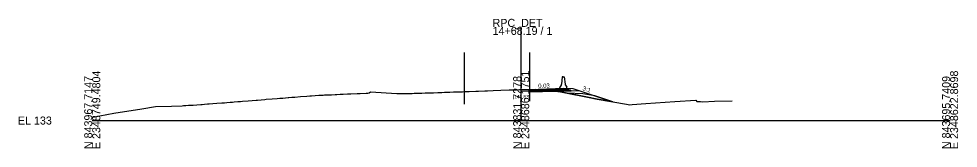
# Model space of a CAD drawing. Extents: x -26 to 2348728, y -10 to 843971.
# Drawn here: x -25.7 to 302.8, y 5990.3 to 6035.6 of the extents above; entities that cross this region are included whole.
import ezdxf

# ---------------------------------------------------------------- set-up
doc = ezdxf.new("R2010")
doc.units = 0
for name, color, linetype in [('Default', 7, 'Continuous'), ('Exist Cross Section Cell', 7, 'Continuous'), ('Exist XS Center Line Elevation Label', 7, 'Continuous'), ('Exist XS Ground Line', 7, 'Continuous'), ('Old_Level_1', 7, 'Continuous'), ('Prop CMT Pvmt Course 1', 7, 'Continuous'), ('Prop CMT Pvmt Course 2', 7, 'Continuous'), ('Prop CMT Pvmt Course 3', 7, 'Continuous'), ('Prop CMT Pvmt Surface', 7, 'Continuous'), ('Prop CMT Pvmt Surface Shoulder', 7, 'Continuous'), ('Prop CMT Shld Paved Course 1', 7, 'Continuous'), ('Prop CMT Shld Paved Course 2', 7, 'Continuous'), ('Prop CMT Shld Paved Course 3', 7, 'Continuous'), ('Prop CMT Slope Grass', 7, 'Continuous'), ('Prop CMT Subgrade Earthwork', 7, 'Continuous'), ('Prop XS Earthwork Shape', 7, 'Continuous'), ('Prop XS Side Slope Text', 7, 'Continuous'), ('Scratch_Level_2', 7, 'Continuous'), ('Scratch_Level_6', 7, 'Continuous'), ('Typical Median Barrier CELL', 7, 'Continuous')]:
    doc.layers.add(name, color=color, linetype=linetype)

# ---------------------------------------------------------------- blocks, each defined once
blk = doc.blocks.new('TYPE T DOUBLE FACE BARRIER')
at = {"layer": 'Typical Median Barrier CELL'}
for p, q in [((-0.33, 3.83), (-0.6, 1.3)), ((0, 3.83), (-0.33, 3.83)), ((0, 3.83), (0.33, 3.83)), ((0.33, 3.83), (0.6, 1.3)), ((-0.75, 0.91), (-1.21, 0.25)), ((-1.21, -0.17), (-1.21, 0.25)), ((0, 0), (0, 0)), ((0.75, 0.91), (1.21, 0.25)), ((1.21, -0.17), (1.21, 0.25)), ((-1.21, -0.17), (1.21, -0.17))]:
    blk.add_line(p, q, dxfattribs=at)
for centre, start, end in [((-1.43, 1.38), 325.0039, 353.9447), ((1.43, 1.38), 186.0553, 214.9937)]:
    blk.add_arc(centre, 0.833, start, end, dxfattribs=at)

msp = doc.modelspace()

# ---------------------------------------------------------------- linework, layer by layer
at = {"layer": 'Exist Cross Section Cell'}
for p, q in [((150, 6000), (150, 6032.79)), ((0, 6000), (150, 6000)), ((150, 6000), (300, 6000))]:
    msp.add_line(p, q, dxfattribs=at)
at = {"layer": 'Exist XS Ground Line'}
msp.add_lwpolyline([(0, 6001.27), (0.21, 6001.18), (7.54, 6002.54), (17.3, 6004.15), (22.1, 6004.95), (27.67, 6005.09), (31.39, 6005.19), (31.86, 6005.21), (32.71, 6005.25), (33.7, 6005.33), (34.27, 6005.38), (34.73, 6005.41), (35.26, 6005.42), (36.54, 6005.53), (38, 6005.64), (38.41, 6005.67), (39.26, 6005.73), (40.35, 6005.82), (40.85, 6005.86), (42.15, 6005.95), (43.59, 6006.05), (45.28, 6006.17), (46.24, 6006.24), (47.03, 6006.32), (48.24, 6006.41), (49, 6006.46), (49.62, 6006.52), (50.96, 6006.63), (51.83, 6006.71), (52.6, 6006.77), (54.56, 6006.92), (57.29, 6007.14), (57.82, 6007.18), (60.32, 6007.39), (60.8, 6007.43), (62.87, 6007.57), (64.69, 6007.72), (65.6, 6007.8), (66.67, 6007.89), (68.47, 6008.02), (68.8, 6008.04), (69.75, 6008.13), (70.85, 6008.21), (72.86, 6008.37), (75, 6008.56), (76.12, 6008.66), (76.72, 6008.7), (79.22, 6008.85), (79.65, 6008.88), (80.74, 6008.92), (81.21, 6008.95), (82.22, 6008.99), (83.61, 6009.05), (84.94, 6009.11), (85.51, 6009.13), (86.72, 6009.19), (87.41, 6009.22), (87.73, 6009.23), (89.28, 6009.3), (90.47, 6009.35), (92.62, 6009.45), (93.21, 6009.48), (93.69, 6009.5), (95.77, 6009.6), (96.4, 6009.64), (96.79, 6009.67), (97.27, 6010), (106.54, 6009.47), (107.35, 6009.43), (109.39, 6009.46), (109.98, 6009.46), (110.42, 6009.47), (111.87, 6009.52), (112.56, 6009.54), (113.77, 6009.58), (115.31, 6009.62), (116.39, 6009.65), (118.03, 6009.68), (118.5, 6009.69), (119.38, 6009.72), (120.82, 6009.78), (122.26, 6009.84), (123.13, 6009.88), (123.55, 6009.9), (125.05, 6009.95), (126.33, 6010), (128.21, 6010.06), (128.81, 6010.08), (129.45, 6010.1), (130.01, 6010.13), (131.85, 6010.17), (134.1, 6010.26), (134.59, 6010.28), (135.03, 6010.29), (137.34, 6010.39), (138.17, 6010.42), (140.18, 6010.48), (142.86, 6010.6), (145.85, 6010.71), (147.56, 6010.77), (148.35, 6010.8), (149.45, 6010.82), (150, 6010.83), (151.12, 6010.86), (151.76, 6010.88), (152.94, 6010.92), (153.48, 6010.92), (153.85, 6010.92), (155.04, 6010.93), (155.66, 6010.92), (156.57, 6010.9), (158.2, 6010.7), (163.81, 6010.02), (173.25, 6008.13), (176.56, 6007.49), (186.88, 6005.74), (188.05, 6005.55), (188.87, 6005.6), (193.62, 6005.95), (203.76, 6006.65), (211.03, 6007.19), (211.45, 6006.69), (212.73, 6006.62), (213.55, 6006.55), (217.66, 6006.74), (223.74, 6006.87)], dxfattribs=at)
at = {"layer": 'Prop CMT Pvmt Course 1'}
for p, q in [((152.94, 6010.92), (162, 6011.19)), ((162.01, 6010.94), (152.94, 6010.66)), ((152.94, 6010.92), (152.94, 6010.66)), ((162, 6011.19), (162.01, 6010.94))]:
    msp.add_line(p, q, dxfattribs=at)
at = {"layer": 'Prop CMT Pvmt Course 2'}
for p, q in [((152.94, 6010.66), (162.01, 6010.94)), ((152.94, 6010.66), (152.94, 6010.33)), ((162.03, 6010.6), (152.94, 6010.33)), ((162.01, 6010.94), (162.03, 6010.6))]:
    msp.add_line(p, q, dxfattribs=at)
at = {"layer": 'Prop CMT Pvmt Course 3'}
for p, q in [((152.94, 6010.33), (162.03, 6010.6)), ((152.94, 6010.33), (152.94, 6010)), ((162.04, 6010.27), (152.94, 6010)), ((162.03, 6010.6), (162.04, 6010.27))]:
    msp.add_line(p, q, dxfattribs=at)
at = {"layer": 'Prop CMT Pvmt Surface'}
msp.add_line((152.94, 6010.92), (162, 6011.19), dxfattribs=at)
at = {"layer": 'Prop CMT Pvmt Surface Shoulder'}
msp.add_line((162, 6011.19), (166, 6011.31), dxfattribs=at)
at = {"layer": 'Prop CMT Shld Paved Course 1'}
for p, q in [((152.94, 6010.66), (152.94, 6010.92)), ((162, 6011.19), (166, 6011.31)), ((162.01, 6010.94), (162, 6011.19)), ((166.26, 6011.06), (162.01, 6010.94)), ((166, 6011.31), (166.27, 6011.06))]:
    msp.add_line(p, q, dxfattribs=at)
at = {"layer": 'Prop CMT Shld Paved Course 2'}
for p, q in [((152.94, 6010.33), (152.94, 6010.66)), ((162.01, 6010.94), (166.26, 6011.06)), ((162.03, 6010.6), (162.01, 6010.94)), ((166.62, 6010.74), (162.03, 6010.6)), ((166.27, 6011.06), (166.62, 6010.74))]:
    msp.add_line(p, q, dxfattribs=at)
at = {"layer": 'Prop CMT Shld Paved Course 3'}
for p, q in [((152.94, 6010), (152.94, 6010.33)), ((162.03, 6010.6), (166.62, 6010.74)), ((162.04, 6010.27), (162.03, 6010.6)), ((167.48, 6010.43), (162.04, 6010.27)), ((166.62, 6010.74), (167.12, 6010.76)), ((167.12, 6010.76), (167.48, 6010.43))]:
    msp.add_line(p, q, dxfattribs=at)
at = {"layer": 'Prop CMT Slope Grass'}
for p, q in [((166, 6011.31), (168.01, 6011.25)), ((168.01, 6011.25), (182.09, 6006.55))]:
    msp.add_line(p, q, dxfattribs=at)
at = {"layer": 'Prop CMT Subgrade Earthwork'}
for p, q in [((152.94, 6010), (152.94, 6010.92)), ((152.94, 6010), (162.04, 6010.27)), ((162.04, 6010.27), (167.48, 6010.43)), ((167.48, 6010.43), (170.2, 6010.52))]:
    msp.add_line(p, q, dxfattribs=at)
at = {"layer": 'Prop XS Earthwork Shape'}
for points in [[(152.94, 6010), (152.94, 6010.92), (153.48, 6010.92), (153.85, 6010.92), (155.04, 6010.93), (155.66, 6010.92), (156.57, 6010.9), (158.2, 6010.7), (161.78, 6010.26)], [(167.48, 6010.43), (170.2, 6010.52), (182.09, 6006.55), (176.56, 6007.49), (173.25, 6008.13), (163.81, 6010.02), (161.78, 6010.26), (162.04, 6010.27)]]:
    msp.add_lwpolyline(points, close=True, dxfattribs=at)
at = {"layer": 'Scratch_Level_2'}
for p, q in [((130.01, 6023.79), (130.01, 6005.72)), ((152.94, 6023.79), (152.94, 6006.82))]:
    msp.add_line(p, q, dxfattribs=at)
at = {"layer": 'Scratch_Level_6'}
for p, q in [((171.57, 6009.35), (166.04, 6009.57)), ((175.81, 6008.64), (171.57, 6009.35)), ((182.09, 6006.55), (175.81, 6008.64))]:
    msp.add_line(p, q, dxfattribs=at)
msp.add_lwpolyline([(166.04, 6009.57), (173.25, 6008.14), (173.25, 6008.13), (176.56, 6007.49), (182.09, 6006.55)], dxfattribs=at)

# ---------------------------------------------------------------- block references
at = {"layer": 'Old_Level_1', "rotation": 1.7183580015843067}
msp.add_blockref('TYPE T DOUBLE FACE BARRIER', (164.79, 6011.44), dxfattribs=at)

# ---------------------------------------------------------------- texts
at = {"layer": 'Default'}
msp.add_text('0.03', height=1.5, rotation=1.7184, dxfattribs=at).set_placement((155.98, 6011.38))
at = {"layer": 'Exist Cross Section Cell'}
for s, p in [('RPC_DET', (140, 6032.79)), ('14+68.19 / 1', (140, 6029.99)), ('EL 133', (-26, 5998.6))]:
    msp.add_text(s, height=2.8, dxfattribs=at).set_placement(p)
for s, p in [('E 2348749.4804', (2.8, 5990)), ('N 843831.7278', (150, 5990)), ('E 2348686.1751', (152.8, 5990)), ('E 2348622.8698', (302.8, 5990)), ('N 843967.7147', (0, 5990)), ('N 843695.7409', (300, 5990))]:
    msp.add_text(s, height=2.8, rotation=90, dxfattribs=at).set_placement(p)
at = {"layer": 'Exist XS Center Line Elevation Label'}
msp.add_text('143.83', height=1.2, dxfattribs=at).set_placement((147.55, 6007.76))
at = {"layer": 'Prop XS Side Slope Text'}
msp.add_text('3:1', height=1.5, rotation=341.5668, dxfattribs=at).set_placement((171.35, 6010.67))

doc.saveas('drawing.dxf')
